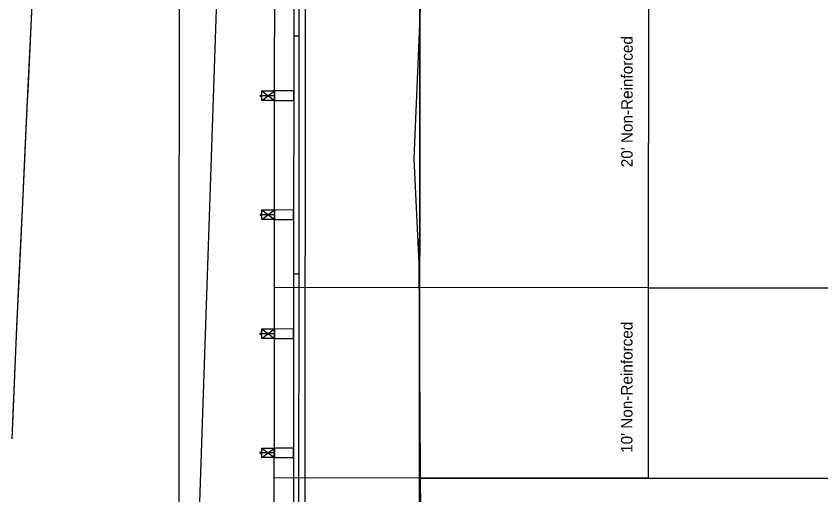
# Model space of a CAD drawing. Extents: x 18543285 to 18543485, y 7434209 to 7435438.
# Drawn here: x 18543351.49 to 18543393.73, y 7434673.55 to 7434698.69 of the extents above; entities that cross this region are included whole.
import ezdxf

# ---------------------------------------------------------------- set-up
doc = ezdxf.new("R2010")
doc.units = 0
for name, color, linetype in [('_CIVIL_CONSTRUCTION', 7, 'Continuous'), ('Contours Major', 7, 'Continuous'), ('Dimensions', 7, 'Continuous'), ('Draft_1', 7, 'Continuous'), ('EdgeUnpaved', 7, 'Continuous'), ('EXT_SNP', 7, 'Continuous'), ('MeshTop', 7, 'Continuous'), ('Sawcut', 7, 'Continuous'), ('Terrain', 7, 'Continuous'), ('TL_ForeSlope', 7, 'Continuous'), ('TL_Grading', 7, 'Continuous'), ('TL_GroundIntercept', 7, 'Continuous')]:
    doc.layers.add(name, color=color, linetype=linetype)

msp = doc.modelspace()

# ---------------------------------------------------------------- linework, layer by layer
at = {"layer": '_CIVIL_CONSTRUCTION'}
msp.add_line((18543372.717, 7434758.131), (18543372.483, 7434398.131), dxfattribs=at)
at = {"layer": 'Contours Major'}
msp.add_line((18543366.494, 7434414.304), (18543366.721, 7434764.553), dxfattribs=at)
msp.add_lwpolyline([(18543365.016, 7434626.011), (18543365.02, 7434631.761), (18543365.02, 7434632.261), (18543365.024, 7434638.011), (18543365.024, 7434638.511), (18543365.056, 7434688.511), (18543365.06, 7434694.261), (18543365.06, 7434694.761), (18543365.065, 7434700.511), (18543365.064, 7434701.011), (18543365.085, 7434732.261), (18543365.086, 7434734.886), (18543365.101, 7434758.323), (18543365.101, 7434758.823), (18543365.134, 7434759.303)], dxfattribs=at)
at = {"layer": 'Dimensions'}
for p, q in [((18543352.113, 7434694.621), (18543352.35, 7434699.615)), ((18543351.876, 7434689.627), (18543352.113, 7434694.621)), ((18543351.639, 7434684.632), (18543351.876, 7434689.627)), ((18543351.49, 7434681.492), (18543351.639, 7434684.632)), ((18543351.282, 7434676.497), (18543351.49, 7434681.492))]:
    msp.add_line(p, q, dxfattribs=at)
at = {"layer": 'Draft_1'}
msp.add_lwpolyline([(18543384.77, 7434781.083), (18543372.9, 7434787.863), (18543372.96, 7434740.606), (18543372.8, 7434701.585), (18543372.37, 7434691.21), (18543372.62, 7434685.7), (18543372.86, 7434650.748), (18543372.86, 7434601.252), (18543372.78, 7434549.829), (18543372.8, 7434512.681), (18543372.38, 7434462.376), (18543372.39, 7434412.042), (18543372.69, 7434360.71), (18543372.51, 7434311.653), (18543372.28, 7434264.026), (18543372.36, 7434218.914)], dxfattribs=at)
at = {"layer": 'EdgeUnpaved'}
msp.add_lwpolyline([(18543366.95, 7434783.457), (18543367.08, 7434760.542), (18543365.95, 7434740.647), (18543362.08, 7434701.65), (18543360.3, 7434648.83), (18543359.65, 7434601.121), (18543356.68, 7434548.03), (18543360.21, 7434529.205), (18543361.5, 7434513.228), (18543365.09, 7434461.857), (18543364.63, 7434411.718), (18543364.49, 7434411.599), (18543365.08, 7434359.945), (18543365.18, 7434311.057), (18543365.28, 7434264.086), (18543364.89, 7434219.782)], dxfattribs=at)
at = {"layer": 'EXT_SNP'}
msp.add_lwpolyline([(18543366.95, 7434783.457), (18543367.08, 7434760.542), (18543365.95, 7434740.647), (18543362.08, 7434701.65), (18543360.3, 7434648.83), (18543359.65, 7434601.121), (18543356.68, 7434548.03), (18543360.21, 7434529.205), (18543361.5, 7434513.228), (18543365.09, 7434461.857), (18543364.63, 7434411.718), (18543364.49, 7434411.599), (18543365.08, 7434359.945), (18543365.18, 7434311.057), (18543365.28, 7434264.086), (18543364.89, 7434219.782)], dxfattribs=at)
at = {"layer": 'MeshTop'}
msp.add_lwpolyline([(18543360.016, 7434626.014), (18543360.02, 7434631.761), (18543360.02, 7434632.262), (18543360.024, 7434638.011), (18543360.024, 7434638.512), (18543360.056, 7434688.514), (18543360.06, 7434694.261), (18543360.06, 7434694.762), (18543360.065, 7434700.511), (18543360.064, 7434701.011), (18543360.085, 7434732.264), (18543360.086, 7434734.889), (18543360.101, 7434758.323), (18543360.101, 7434758.996), (18543360.135, 7434759.477)], dxfattribs=at)
msp.add_lwpolyline([(18543360.016, 7434626.014), (18543360.02, 7434631.761), (18543360.02, 7434632.262), (18543360.024, 7434638.011), (18543360.024, 7434638.512), (18543360.056, 7434688.514), (18543360.06, 7434694.261), (18543360.06, 7434694.762), (18543360.065, 7434700.511), (18543360.064, 7434701.011), (18543360.085, 7434732.264), (18543360.086, 7434734.889), (18543360.101, 7434758.323), (18543360.101, 7434758.996), (18543360.135, 7434759.477)], dxfattribs=at)
msp.add_lwpolyline([(18543360.016, 7434626.014), (18543360.02, 7434631.761), (18543360.02, 7434632.262), (18543360.024, 7434638.011), (18543360.024, 7434638.512), (18543360.056, 7434688.514), (18543360.06, 7434694.261), (18543360.06, 7434694.762), (18543360.065, 7434700.511), (18543360.064, 7434701.011), (18543360.085, 7434732.264), (18543360.086, 7434734.889), (18543360.101, 7434758.323), (18543360.101, 7434758.996), (18543360.135, 7434759.477)], dxfattribs=at)
at = {"layer": 'Sawcut'}
msp.add_lwpolyline([(18543368.55, 7434414.302), (18543372.494, 7434414.3), (18543372.663, 7434674.434), (18543396.663, 7434674.418), (18543396.486, 7434402.372), (18543399.487, 7434402.37)], dxfattribs=at)
at = {"layer": 'TL_ForeSlope'}
for p, q in [((18543372.663, 7434674.434), (18543372.719, 7434761.085)), ((18543372.663, 7434674.434), (18543372.717, 7434758.114)), ((18543384.682, 7434704.426), (18543384.669, 7434684.426)), ((18543384.669, 7434684.426), (18543365.044, 7434684.439)), ((18543384.669, 7434684.426), (18543365.054, 7434684.439)), ((18543384.669, 7434684.426), (18543384.663, 7434674.426)), ((18543384.669, 7434684.426), (18543408.294, 7434684.411)), ((18543384.669, 7434684.426), (18543408.285, 7434684.411)), ((18543384.663, 7434674.426), (18543365.038, 7434674.439)), ((18543384.663, 7434674.426), (18543365.047, 7434674.439)), ((18543372.494, 7434414.3), (18543372.663, 7434674.434)), ((18543384.663, 7434674.426), (18543408.278, 7434674.411)), ((18543384.663, 7434674.426), (18543408.278, 7434674.411))]:
    msp.add_line(p, q, dxfattribs=at)
at = {"layer": 'TL_Grading'}
for p, q in [((18543366.071, 7434710.135), (18543366.063, 7434697.635)), ((18543366.342, 7434710.135), (18543366.334, 7434697.635)), ((18543366.063, 7434697.635), (18543366.055, 7434685.135)), ((18543366.334, 7434697.635), (18543366.063, 7434697.635)), ((18543366.334, 7434697.635), (18543366.063, 7434697.635)), ((18543366.334, 7434697.635), (18543366.326, 7434685.135)), ((18543364.393, 7434694.261), (18543365.06, 7434694.761)), ((18543364.394, 7434694.761), (18543365.06, 7434694.261)), ((18543365.06, 7434694.761), (18543365.06, 7434694.261)), ((18543366.061, 7434694.76), (18543365.06, 7434694.761)), ((18543366.061, 7434694.26), (18543366.061, 7434694.76)), ((18543364.296, 7434694.512), (18543364.289, 7434694.512)), ((18543365.06, 7434694.511), (18543364.393, 7434694.511)), ((18543365.06, 7434694.261), (18543366.061, 7434694.26)), ((18543364.292, 7434688.262), (18543364.285, 7434688.262)), ((18543364.389, 7434688.011), (18543365.056, 7434688.511)), ((18543365.056, 7434688.261), (18543364.389, 7434688.261)), ((18543364.39, 7434688.511), (18543365.056, 7434688.011)), ((18543365.056, 7434688.511), (18543365.056, 7434688.011)), ((18543366.057, 7434688.51), (18543365.056, 7434688.511)), ((18543366.057, 7434688.01), (18543366.057, 7434688.51)), ((18543365.056, 7434688.011), (18543366.057, 7434688.01)), ((18543366.055, 7434685.135), (18543366.047, 7434672.635)), ((18543366.326, 7434685.135), (18543366.055, 7434685.135)), ((18543366.326, 7434685.135), (18543366.055, 7434685.135)), ((18543366.326, 7434685.135), (18543366.318, 7434672.635)), ((18543364.288, 7434682.012), (18543364.281, 7434682.012)), ((18543364.385, 7434682.261), (18543365.052, 7434681.761)), ((18543364.385, 7434681.761), (18543365.052, 7434682.261)), ((18543365.052, 7434682.011), (18543364.385, 7434682.011)), ((18543365.052, 7434682.261), (18543365.052, 7434681.761)), ((18543366.053, 7434682.26), (18543365.052, 7434682.261)), ((18543366.053, 7434681.76), (18543366.053, 7434682.26)), ((18543365.052, 7434681.761), (18543366.053, 7434681.76)), ((18543364.381, 7434676.011), (18543365.048, 7434675.511)), ((18543364.381, 7434675.511), (18543365.048, 7434676.011)), ((18543365.048, 7434676.011), (18543365.048, 7434675.511)), ((18543366.049, 7434676.01), (18543365.048, 7434676.011)), ((18543366.049, 7434675.51), (18543366.049, 7434676.01)), ((18543364.284, 7434675.762), (18543364.277, 7434675.762)), ((18543365.048, 7434675.761), (18543364.381, 7434675.761)), ((18543365.048, 7434675.511), (18543366.049, 7434675.51))]:
    msp.add_line(p, q, dxfattribs=at)
for points in [[(18543365.06, 7434694.761), (18543365.06, 7434694.261), (18543364.393, 7434694.261), (18543364.394, 7434694.761)], [(18543365.056, 7434688.511), (18543365.056, 7434688.011), (18543364.389, 7434688.011), (18543364.39, 7434688.511)], [(18543365.052, 7434682.261), (18543365.052, 7434681.761), (18543364.385, 7434681.761), (18543364.385, 7434682.261)], [(18543365.048, 7434676.011), (18543365.048, 7434675.511), (18543364.381, 7434675.511), (18543364.381, 7434676.011)]]:
    msp.add_lwpolyline(points, close=True, dxfattribs=at)
for points in [[(18543364.35, 7434694.531), (18543364.296, 7434694.531), (18543364.296, 7434694.492), (18543364.35, 7434694.492)], [(18543364.393, 7434694.545), (18543364.35, 7434694.545), (18543364.35, 7434694.478), (18543364.393, 7434694.478)], [(18543364.346, 7434688.281), (18543364.292, 7434688.281), (18543364.292, 7434688.242), (18543364.346, 7434688.242)], [(18543364.389, 7434688.295), (18543364.346, 7434688.295), (18543364.346, 7434688.228), (18543364.389, 7434688.228)], [(18543364.342, 7434682.031), (18543364.288, 7434682.031), (18543364.288, 7434681.992), (18543364.342, 7434681.992)], [(18543364.385, 7434682.045), (18543364.342, 7434682.045), (18543364.342, 7434681.978), (18543364.385, 7434681.978)], [(18543364.338, 7434675.781), (18543364.284, 7434675.781), (18543364.284, 7434675.742), (18543364.338, 7434675.742)], [(18543364.381, 7434675.795), (18543364.338, 7434675.795), (18543364.338, 7434675.728), (18543364.381, 7434675.728)]]:
    msp.add_lwpolyline(points, dxfattribs=at)
at = {"layer": 'TL_GroundIntercept'}
msp.add_lwpolyline([(18543351.32, 7434677.401), (18543351.49, 7434681.492), (18543351.533, 7434682.401), (18543351.63, 7434684.451), (18543351.771, 7434687.401), (18543351.824, 7434688.52), (18543352.008, 7434692.401), (18543352.096, 7434694.266), (18543352.12, 7434694.769), (18543352.245, 7434697.401), (18543352.393, 7434700.519), (18543352.417, 7434701.019), (18543352.483, 7434702.401), (18543352.72, 7434707.4), (18543352.804, 7434709.175), (18543352.901, 7434711.22), (18543352.929, 7434711.8), (18543352.957, 7434712.4), (18543353.077, 7434714.925), (18543353.093, 7434715.265), (18543351.592, 7434715.77), (18543351.597, 7434723.27), (18543351.597, 7434723.27), (18543353.669, 7434727.4)], dxfattribs=at)

# ---------------------------------------------------------------- texts
at = {"layer": 'Terrain'}
for s, p in [("20' Non-Reinforced", (18543383.85, 7434690.756)), ("10' Non-Reinforced", (18543383.841, 7434675.756))]:
    msp.add_text(s, height=0.6, rotation=89.9628, dxfattribs=at).set_placement(p)

doc.saveas('drawing.dxf')
